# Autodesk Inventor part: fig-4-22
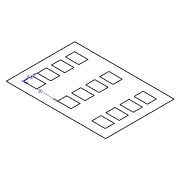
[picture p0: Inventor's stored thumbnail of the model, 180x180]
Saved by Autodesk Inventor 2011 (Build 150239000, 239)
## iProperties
Created: 2004-05
Part Number: fig-4-22
Document SubType Name: Modeling
Designer: CADCIM Technologies
Manufacturer: Standard
Standards Organization: Custom
Density: 1 g/cm^3
Author: CADCIM Technologies
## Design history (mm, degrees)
sketch "Sketch1"
  geometry: L1 (7.752, 6.176)-(65.752, 6.176); L2 (65.752, 6.176)-(65.752, 46.176); L3 (65.752, 46.176)-(7.752, 46.176); L4 (7.752, 46.176)-(7.752, 6.176); L5 (12.752, 11.176)-(20.543, 11.176); L6 (20.543, 11.176)-(20.543, 16.473); L7 (20.543, 16.473)-(12.752, 16.473); L8 (12.752, 16.473)-(12.752, 11.176); L9 (32.752, 11.176)-(40.543, 11.176); L10 (40.543, 11.176)-(40.543, 16.473); L11 (40.543, 16.473)-(32.752, 16.473); L12 (32.752, 16.473)-(32.752, 11.176); L13 (52.752, 11.176)-(60.543, 11.176); L14 (60.543, 11.176)-(60.543, 16.473); L15 (60.543, 16.473)-(52.752, 16.473); L16 (52.752, 16.473)-(52.752, 11.176); L17 (12.752, 19.376)-(20.543, 19.376); L18 (20.543, 19.376)-(20.543, 24.673); L19 (20.543, 24.673)-(12.752, 24.673); L20 (12.752, 24.673)-(12.752, 19.376); L21 (32.752, 19.376)-(40.543, 19.376); L22 (40.543, 19.376)-(40.543, 24.673); L23 (40.543, 24.673)-(32.752, 24.673); L24 (32.752, 24.673)-(32.752, 19.376); L25 (52.752, 19.376)-(60.543, 19.376); L26 (60.543, 19.376)-(60.543, 24.673); L27 (60.543, 24.673)-(52.752, 24.673); L28 (52.752, 24.673)-(52.752, 19.376); L29 (12.752, 27.576)-(20.543, 27.576); L30 (20.543, 27.576)-(20.543, 32.873); L31 (20.543, 32.873)-(12.752, 32.873); L32 (12.752, 32.873)-(12.752, 27.576); L33 (32.752, 27.576)-(40.543, 27.576); L34 (40.543, 27.576)-(40.543, 32.873); L35 (40.543, 32.873)-(32.752, 32.873); L36 (32.752, 32.873)-(32.752, 27.576); L37 (52.752, 27.576)-(60.543, 27.576); L38 (60.543, 27.576)-(60.543, 32.873); L39 (60.543, 32.873)-(52.752, 32.873); L40 (52.752, 32.873)-(52.752, 27.576); L41 (12.752, 35.776)-(20.543, 35.776); L42 (20.543, 35.776)-(20.543, 41.073); L43 (20.543, 41.073)-(12.752, 41.073); L44 (12.752, 41.073)-(12.752, 35.776); L45 (32.752, 35.776)-(40.543, 35.776); L46 (40.543, 35.776)-(40.543, 41.073); L47 (40.543, 41.073)-(32.752, 41.073); L48 (32.752, 41.073)-(32.752, 35.776); L49 (52.752, 35.776)-(60.543, 35.776); L50 (60.543, 35.776)-(60.543, 41.073); L51 (60.543, 41.073)-(52.752, 41.073); L52 (52.752, 41.073)-(52.752, 35.776)
  constraints: 104 end point, 4 parallel, 3 horizontal, 2 perpendicular, 1 vertical, 88 other
  dimensions: "d14" = 20 distance of L5.start L9.start; "d17" = 8.2 distance of L5.start L17.start
